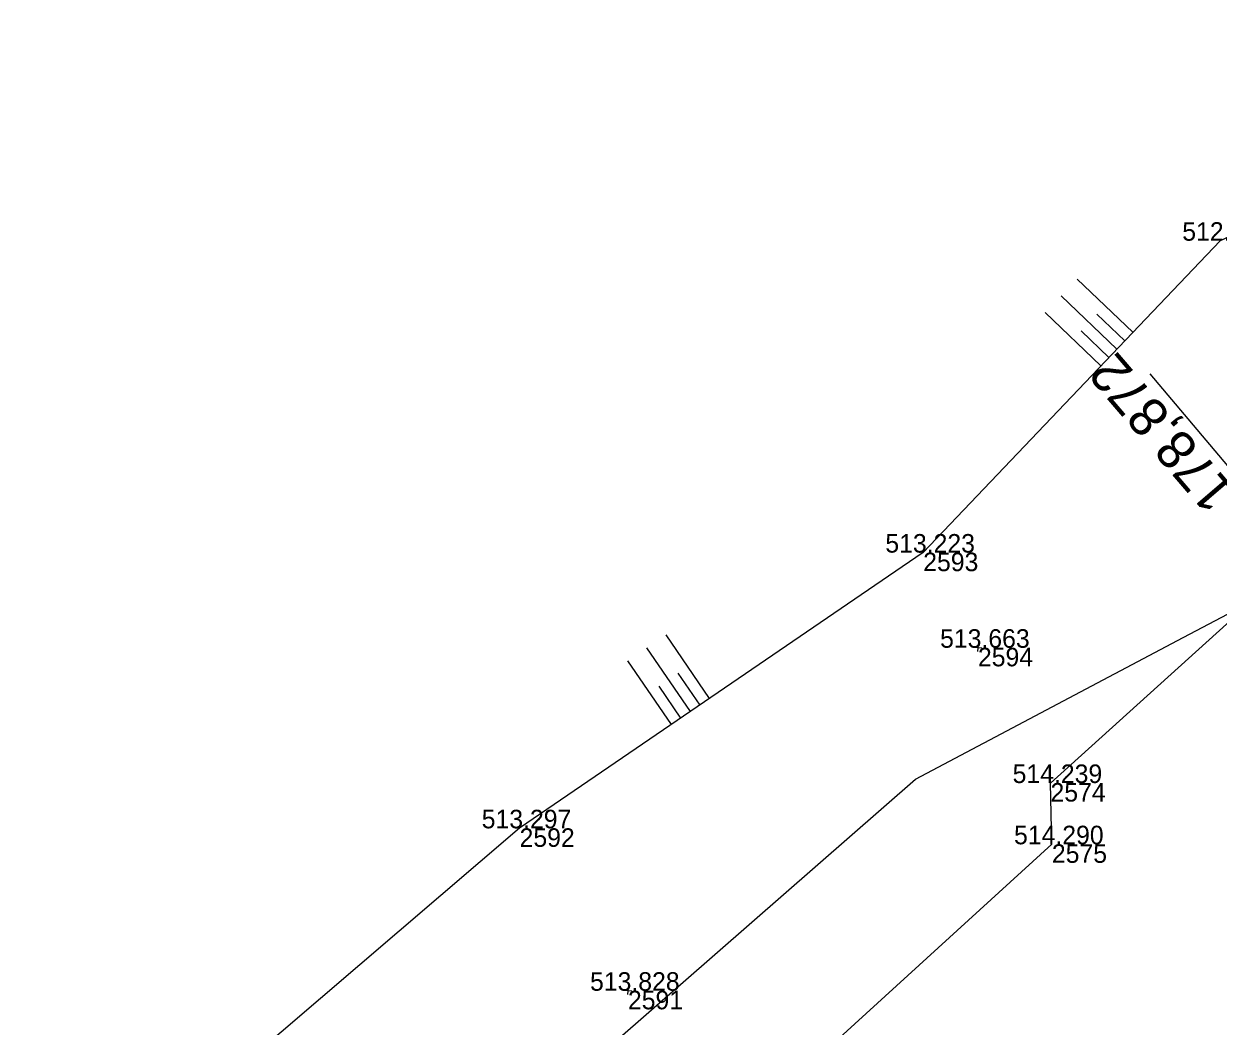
# Model space of a CAD drawing. Extents: x -1234191 to 23050, y -1290331 to -741191.
# Drawn here: x -865317 to -865239.7, y -1104800.7 to -1104735.8 of the extents above; entities that cross this region are included whole.
import ezdxf

# ---------------------------------------------------------------- set-up
doc = ezdxf.new("R2010")
doc.units = 0
for name, color, linetype in [('Vrstva 16', 7, 'Continuous'), ('Vrstva 3', 7, 'Continuous'), ('Vrstva 48', 7, 'Continuous'), ('Vrstva 49', 7, 'Continuous'), ('Vrstva 53', 7, 'Continuous'), ('Vrstva 6', 7, 'Continuous'), ('Vrstva 60', 7, 'Continuous'), ('Vrstva 61', 7, 'Continuous')]:
    doc.layers.add(name, color=color, linetype=linetype)

msp = doc.modelspace()

# ---------------------------------------------------------------- linework, layer by layer
at = {"layer": 'Vrstva 16'}
msp.add_lwpolyline([(-865364.804, -1104865.035), (-865347.352, -1104878.663), (-865335.605, -1104868.404), (-865321.309, -1104855.308), (-865306.813, -1104842.156), (-865307.637, -1104841.221), (-865285.52, -1104820.848), (-865269.807, -1104806.574), (-865250.423, -1104788.913), (-865250.512, -1104784.949), (-865237.108, -1104772.85)], dxfattribs=at)
at = {"layer": 'Vrstva 48'}
for p, q in [((-865245.176, -1104755.783), (-865248.797, -1104752.335)), ((-865246.211, -1104756.87), (-865249.831, -1104753.421)), ((-865247.245, -1104757.956), (-865250.866, -1104754.507)), ((-865245.693, -1104756.326), (-865247.504, -1104754.602)), ((-865246.728, -1104757.413), (-865248.538, -1104755.689)), ((-865272.58, -1104779.479), (-865275.4, -1104775.35)), ((-865273.819, -1104780.325), (-865276.638, -1104776.196)), ((-865275.058, -1104781.171), (-865277.877, -1104777.042)), ((-865273.2, -1104779.902), (-865274.609, -1104777.838)), ((-865274.438, -1104780.748), (-865275.848, -1104778.683))]:
    msp.add_line(p, q, dxfattribs=at)
at = {"layer": 'Vrstva 49'}
for p, q in [((-865255.19, -1104775.947), (-865255.23, -1104776.445)), ((-865254.961, -1104776.216), (-865255.459, -1104776.176)), ((-865277.62, -1104798.411), (-865278.118, -1104798.371)), ((-865277.849, -1104798.142), (-865277.889, -1104798.64))]:
    msp.add_line(p, q, dxfattribs=at)
msp.add_lwpolyline([(-865171.114, -1104750.378), (-865191.358, -1104740.165), (-865202.899, -1104737.779), (-865216.924, -1104745.887), (-865226.364, -1104743.666), (-865239.531, -1104749.856), (-865258.753, -1104770.039), (-865284.883, -1104787.879), (-865308.11, -1104807.741), (-865326.673, -1104834.815), (-865331.084, -1104845.736), (-865343.979, -1104852.325), (-865358.212, -1104855.226), (-865375.636, -1104870.093), (-865379.598, -1104879.473), (-865375.064, -1104894.679), (-865385.012, -1104905.646), (-865402.355, -1104922.203), (-865421.239, -1104947.821), (-865427.839, -1104950.026), (-865433.692, -1104947.296), (-865439.605, -1104965.607)], dxfattribs=at)
at = {"layer": 'Vrstva 53'}
msp.add_lwpolyline([(-865358.56, -1104832.2), (-865344.31, -1104837.25), (-865331.6, -1104841.01), (-865307.17, -1104827.049), (-865303.449, -1104823.649), (-865290.039, -1104811.399), (-865282.85, -1104805.29), (-865259.25, -1104784.69), (-865241.92, -1104775.54), (-865238.189, -1104773.579), (-865221.09, -1104785.079), (-865205.96, -1104773.969), (-865199.88, -1104780.209), (-865156.1, -1104742.09), (-865117.76, -1104687.139), (-865096.64, -1104634.62), (-865091.196, -1104622.638)], dxfattribs=at)
at = {"layer": 'Vrstva 6'}
msp.add_lwpolyline([(-865208.504, -1104800.677), (-865212.012, -1104796.418), (-865244.056, -1104758.477)], dxfattribs=at)
at = {"layer": 'Vrstva 60'}
for p, q in [((-865258.753, -1104770.039), (-865258.753, -1104770.039)), ((-865255.21, -1104776.196), (-865255.21, -1104776.196)), ((-865250.512, -1104784.949), (-865250.512, -1104784.949)), ((-865284.883, -1104787.879), (-865284.883, -1104787.879)), ((-865250.423, -1104788.913), (-865250.423, -1104788.913)), ((-865277.869, -1104798.391), (-865277.869, -1104798.391))]:
    msp.add_line(p, q, dxfattribs=at)

# ---------------------------------------------------------------- texts
at = {"layer": 'Vrstva 3'}
msp.add_text('km 178,872', height=2.5, rotation=130.62408, dxfattribs=at).set_placement((-865234.904, -1104770.192))
at = {"layer": 'Vrstva 60'}
for s, p in [('2593', (-865258.753, -1104771.239)), ('2594', (-865255.21, -1104777.396)), ('2574', (-865250.512, -1104786.149)), ('2592', (-865284.883, -1104789.079)), ('2575', (-865250.423, -1104790.113)), ('2591', (-865277.869, -1104799.591))]:
    msp.add_text(s, height=1.2, dxfattribs=at).set_placement(p)
at = {"layer": 'Vrstva 61'}
for s, p in [('512.827', (-865241.983, -1104749.856)), ('513.223', (-865261.205, -1104770.039)), ('513.663', (-865257.662, -1104776.196)), ('514.239', (-865252.966, -1104784.949)), ('513.297', (-865287.335, -1104787.879)), ('514.290', (-865252.874, -1104788.913)), ('513.828', (-865280.323, -1104798.391))]:
    msp.add_text(s, height=1.2, dxfattribs=at).set_placement(p)

doc.saveas('drawing.dxf')
